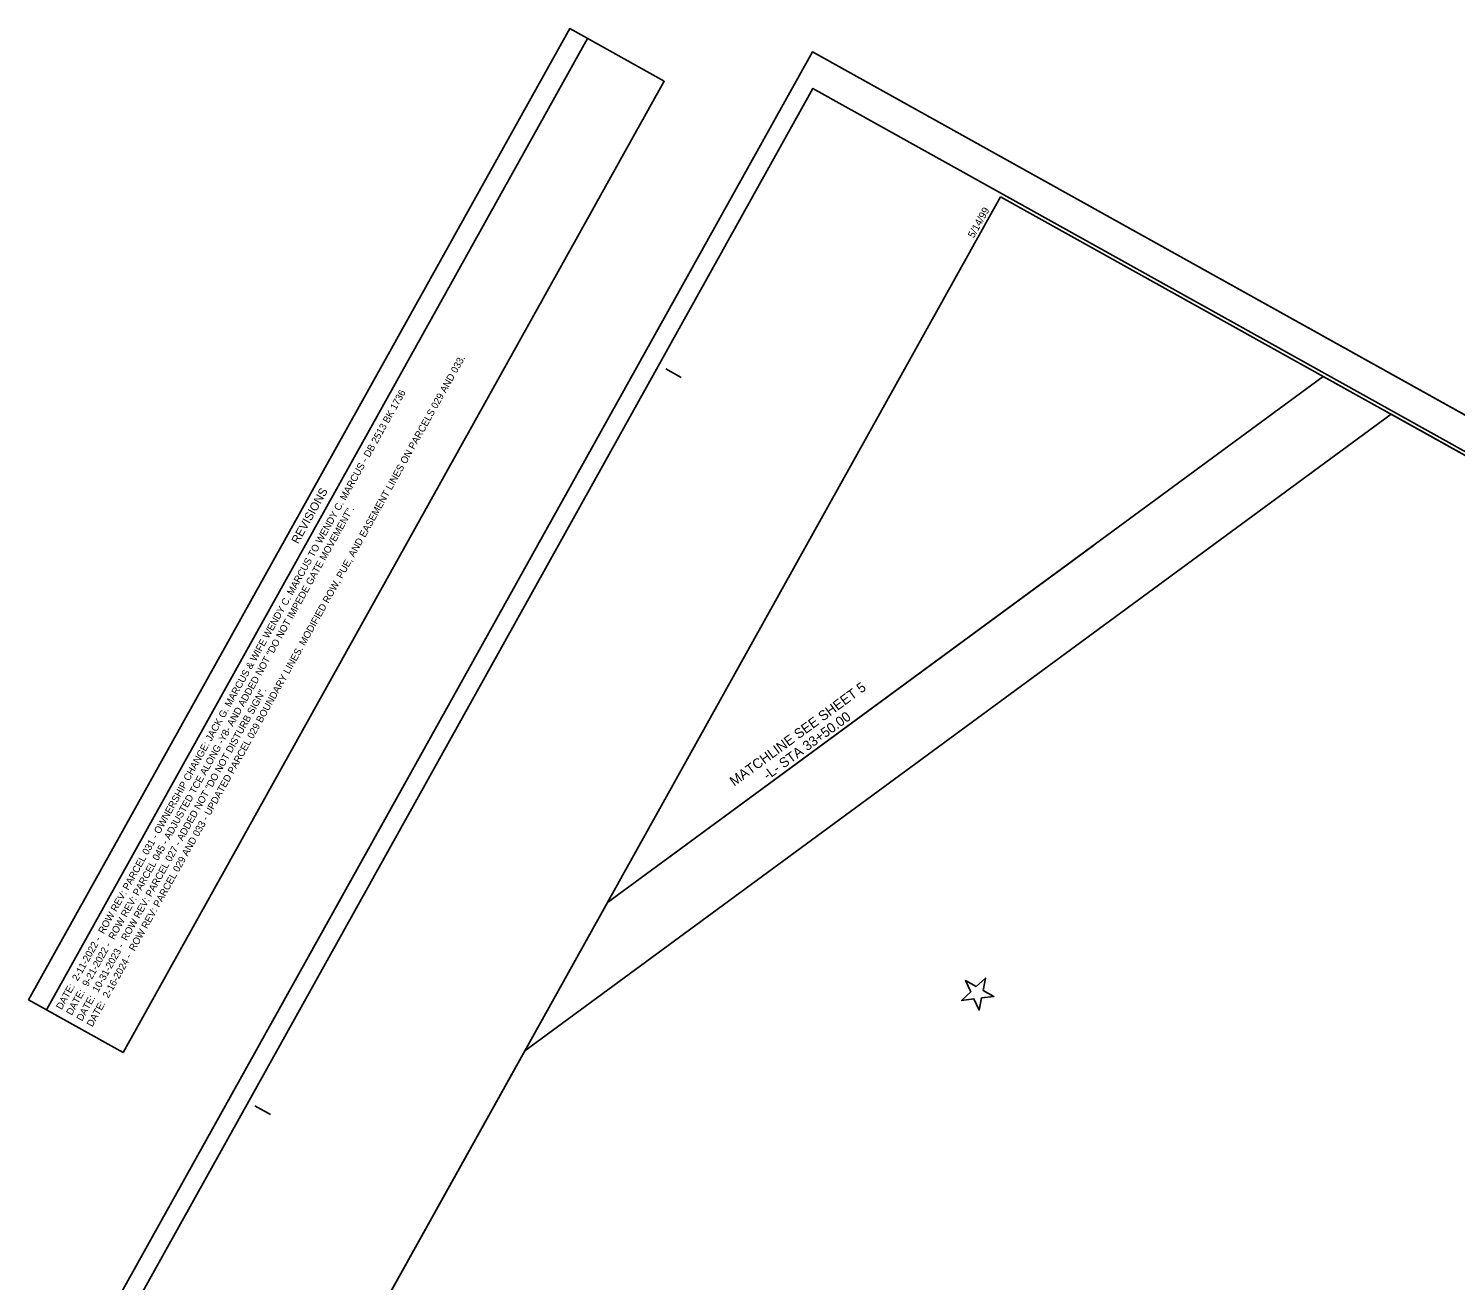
# Model space of a CAD drawing. Extents: x 1763454 to 1765483, y 710212 to 712009.
# Drawn here: x 1763454 to 1764468, y 711119 to 712009 of the extents above; entities that cross this region are included whole.
import ezdxf

# ---------------------------------------------------------------- set-up
doc = ezdxf.new("R2010")
doc.units = 0
for name, color, linetype in [('Default', 7, 'Continuous'), ('Matchline', 7, 'Continuous'), ('Matchline Text', 7, 'Continuous'), ('Prop RDY Traffic Signal CELL', 7, 'Continuous'), ('Sheet Block Revision CELL', 7, 'Continuous'), ('Sheet Border Standard 30in CELL', 7, 'Continuous'), ('Sheet Cutting Line CELL', 7, 'Continuous'), ('Sheet Layout Plan Border', 7, 'Continuous'), ('Sheet Plot Border Inside CELL', 7, 'Continuous'), ('Sheet Plot Border Outside CELL', 7, 'Continuous')]:
    doc.layers.add(name, color=color, linetype=linetype)

msp = doc.modelspace()

# ---------------------------------------------------------------- linework, layer by layer
at = {"layer": 'Default'}
msp.add_lwpolyline([(1763634.2, 710972.3), (1763634.2, 710972.3), (1763806.9, 711282.5), (1764422.6, 711735.1), (1765280.8, 711257.2), (1765145.7, 711014.6), (1765228.4, 710968.6), (1764852.6, 710293.8)], close=True, dxfattribs=at)
at = {"layer": 'Matchline'}
msp.add_line((1764211.1, 711641.9), (1763865.7, 711388), dxfattribs=at)
at = {"layer": 'Prop RDY Traffic Signal CELL'}
msp.add_lwpolyline([(1764127.8, 711328.2), (1764120.1, 711332.5), (1764123.8, 711324.4), (1764117.3, 711318.4), (1764126.1, 711319.5), (1764129.9, 711311.5), (1764131.6, 711320.1), (1764140.3, 711321.2), (1764132.6, 711325.5), (1764134.3, 711334.2), (1764127.8, 711328.2)], dxfattribs=at)
at = {"layer": 'Sheet Block Revision CELL'}
msp.add_line((1763466.9, 711311.6), (1763851.5, 712002.4), dxfattribs=at)
msp.add_lwpolyline([(1763454.2, 711318.7), (1763838.8, 712009.4), (1763906, 711972), (1763521.4, 711281.3)], close=True, dxfattribs=at)
at = {"layer": 'Sheet Border Standard 30in CELL'}
for p, q in [((1764145.9, 711889.2), (1764145.9, 711889.2)), ((1763907.1, 711767.5), (1763918, 711761.4)), ((1763615.1, 711243.3), (1763626.1, 711237.2))]:
    msp.add_line(p, q, dxfattribs=at)
msp.add_lwpolyline([(1765455.5, 711159.9), (1764145, 711889.7), (1763634.2, 710972.3), (1764944.7, 710242.5)], close=True, dxfattribs=at)
at = {"layer": 'Sheet Cutting Line CELL'}
for p, q in [((1764011.3, 711992.8), (1763476.1, 711031.7)), ((1765482.6, 711173.4), (1764011.3, 711992.8))]:
    msp.add_line(p, q, dxfattribs=at)
at = {"layer": 'Sheet Layout Plan Border'}
for p, q in [((1763865.7, 711388), (1764374.3, 711762)), ((1764374.3, 711762), (1765280.8, 711257.2)), ((1763634.2, 710972.3), (1763865.7, 711388))]:
    msp.add_line(p, q, dxfattribs=at)
at = {"layer": 'Sheet Plot Border Inside CELL'}
msp.add_lwpolyline([(1765467.7, 711156), (1764011.7, 711966.8), (1763498.4, 711045), (1764954.4, 710234.2)], close=True, dxfattribs=at)
at = {"layer": 'Sheet Plot Border Outside CELL'}
msp.add_lwpolyline([(1765482.6, 711173.4), (1764011.3, 711992.8), (1763476.1, 711031.7), (1764947.4, 710212.4)], close=True, dxfattribs=at)

# ---------------------------------------------------------------- texts
at = {"layer": 'Matchline Text'}
for s, p in [('MATCHLINE SEE SHEET 5', (1763955.7, 711470.4)), ('-L- STA 33+50.00', (1763979.5, 711474.8))]:
    msp.add_text(s, height=7, rotation=36.2263, dxfattribs=at).set_placement(p)
at = {"layer": 'Sheet Block Revision CELL'}
for s, height, p in [('DATE:  2-16-2024 -  ROW REV: PARCEL 029 AND 033 - UPDATED PARCEL 029 BOUNDARY LINES. MODIFIED ROW, PUE, AND EASEMENT LINES ON PARCELS 029 AND 033.                 ', 5, (1763499.5, 711299.1)), ('DATE:  2-11-2022 -  ROW REV: PARCEL 031 - OWNERSHIP CHANGE: JACK G. MARCUS & WIFE WENDY C. MARCUS TO WENDY C. MARCUS - DB 2513 BK 1736                ', 5, (1763477.7, 711311.3)), ('REVISIONS', 6, (1763645.8, 711642.5)), ('DATE:  9-21-2022 -  ROW REV: PARCEL 045 - ADJUSTED TCE ALONG -Y8- AND ADDED NOT "DO NOT IMPEDE GATE MOVEMENT".                ', 5, (1763484.9, 711307.3)), ('DATE:  10-31-2023 -  ROW REV: PARCEL 027 - ADDED NOT "DO NOT DISTURB SIGN".                ', 5, (1763492.2, 711303.2))]:
    msp.add_text(s, height=height, rotation=60.8875, dxfattribs=at).set_placement(p)
at = {"layer": 'Sheet Border Standard 30in CELL'}
msp.add_text('5/14/99', height=5.25, rotation=60.8875, dxfattribs=at).set_placement((1764126, 711860))

doc.saveas('drawing.dxf')
